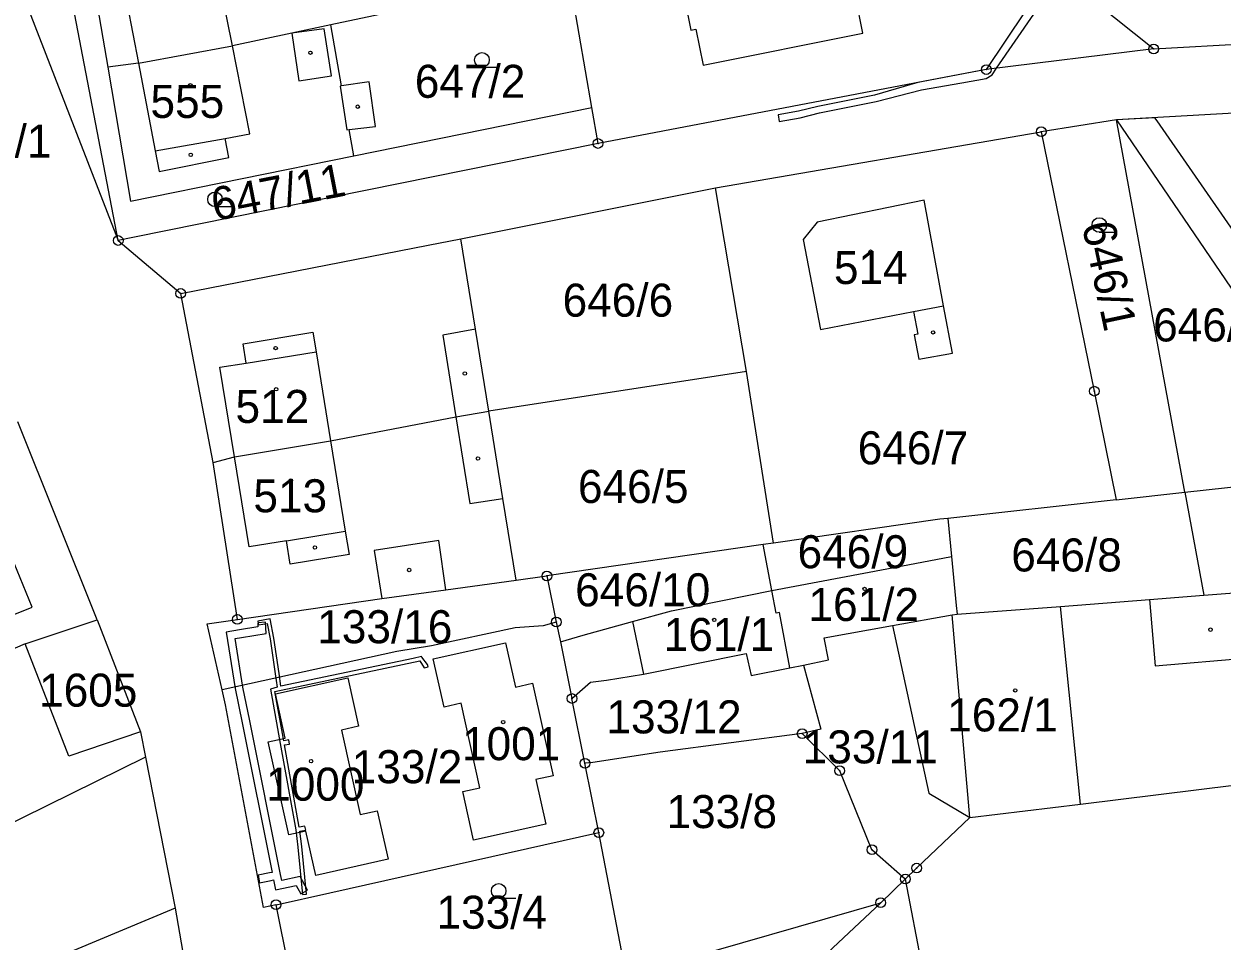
# Model space of a CAD drawing. Extents: x -537341 to -532984, y -1143469 to -1141314.
# Drawn here: x -533782.7 to -533659.4, y -1143007.7 to -1142913.3 of the extents above; entities that cross this region are included whole.
import ezdxf

# ---------------------------------------------------------------- set-up
doc = ezdxf.new("R2010")
doc.units = 0
for name, color, linetype in [('Hranice parcel', 7, 'Continuous'), ('parcelní_č_2000', 7, 'Continuous'), ('Vnitřní kresba', 7, 'Continuous'), ('Věcná břemena k části', 7, 'Continuous'), ('Značky bodu BP', 7, 'Continuous'), ('Značky budov', 7, 'Continuous'), ('Značky kultur', 7, 'Continuous')]:
    doc.layers.add(name, color=color, linetype=linetype)

msp = doc.modelspace()

# ---------------------------------------------------------------- linework, layer by layer
at = {"layer": 'Hranice parcel'}
for p, q in [((-533786.13, -1142901.71), (-533773.02, -1142935.56)), ((-533773.02, -1142935.56), (-533779.04, -1142904.13)), ((-533776.44, -1142903.87), (-533774.1, -1142917.72)), ((-533726.64, -1142908.16), (-533751.13, -1142913.35)), ((-533724.28, -1142921.87), (-533726.64, -1142908.16)), ((-533666.46, -1142915.84), (-533560.9, -1142909.85)), ((-533770.94, -1142917.31), (-533761.27, -1142915.51)), ((-533666.46, -1142915.84), (-533683.69, -1142917.96)), ((-533770.94, -1142917.31), (-533774.1, -1142917.72)), ((-533683.69, -1142917.96), (-533723.64, -1142925.57)), ((-533748.78, -1142926.85), (-533724.28, -1142921.87)), ((-533723.64, -1142925.57), (-533724.28, -1142921.87)), ((-533670.28, -1142923.14), (-533678.04, -1142924.36)), ((-533663.27, -1142961.47), (-533670.28, -1142923.14)), ((-533711.54, -1142930.13), (-533678.04, -1142924.36)), ((-533737.77, -1142935.37), (-533711.54, -1142930.13)), ((-533708.36, -1142949.06), (-533711.54, -1142930.13)), ((-533773.02, -1142935.56), (-533766.59, -1142941.01)), ((-533763.26, -1142958.42), (-533766.59, -1142941.01)), ((-533708.36, -1142949.06), (-533734.89, -1142953.12)), ((-533705.6, -1142966.72), (-533708.36, -1142949.06)), ((-533775.17, -1142974.6), (-533783.36, -1142954.23)), ((-533663.27, -1142961.47), (-533629.48, -1142957.72)), ((-533760.76, -1142974.57), (-533763.26, -1142958.42)), ((-533670.31, -1142962.27), (-533687.66, -1142964.18)), ((-533670.31, -1142962.27), (-533663.27, -1142961.47)), ((-533663.27, -1142961.47), (-533661.32, -1142972.07)), ((-533687.66, -1142964.18), (-533687.28, -1142968.08)), ((-533706.65, -1142966.87), (-533728.91, -1142970.09)), ((-533705.6, -1142966.72), (-533706.65, -1142966.87)), ((-533705.76, -1142971.6), (-533706.65, -1142966.87)), ((-533739.31, -1142971.52), (-533732.07, -1142970.51)), ((-533732.07, -1142970.51), (-533728.91, -1142970.09)), ((-533728.91, -1142970.09), (-533727.94, -1142974.84)), ((-533716.09, -1142973.67), (-533705.76, -1142971.6)), ((-533686.69, -1142974.04), (-533676.05, -1142973.23)), ((-533673.99, -1142993.57), (-533676.05, -1142973.23)), ((-533782.58, -1142977.08), (-533775.17, -1142974.6)), ((-533775.17, -1142974.6), (-533770.72, -1142986.14)), ((-533727.94, -1142974.84), (-533727.52, -1142976.87)), ((-533727.52, -1142976.87), (-533726.33, -1142982.71)), ((-533703.91, -1142979.55), (-533702.51, -1142979.27)), ((-533724.99, -1142989.38), (-533726.33, -1142982.71)), ((-533770.72, -1142986.14), (-533770.2, -1142988.74)), ((-533770.2, -1142988.74), (-533789.42, -1142998.21)), ((-533770.2, -1142988.74), (-533767.15, -1143004.29)), ((-533723.56, -1142996.52), (-533724.99, -1142989.38)), ((-533685.4, -1142994.95), (-533673.99, -1142993.57)), ((-533720.72, -1143011.28), (-533723.56, -1142996.52)), ((-533694.56, -1143003.73), (-533692.03, -1143001.3)), ((-533692.03, -1143001.3), (-533689.17, -1143016.19)), ((-533767.15, -1143004.29), (-533764.49, -1143019.94)), ((-533754.02, -1143017.55), (-533756.78, -1143003.94)), ((-533717.21, -1143010.27), (-533694.56, -1143003.73)), ((-533694.56, -1143003.73), (-533712.73, -1143020.79))]:
    msp.add_line(p, q, dxfattribs=at)
for points in [[(-533689.87, -1142816.17), (-533672.51, -1142910.99), (-533666.46, -1142915.84)], [(-533684.34, -1142886.86), (-533679.73, -1142912.01), (-533683.69, -1142917.96)], [(-533714.09, -1142913.89), (-533713.58, -1142913.79), (-533712.81, -1142917.52), (-533696.39, -1142914.21), (-533697.12, -1142910.54), (-533696.62, -1142910.44), (-533697.36, -1142906.7), (-533697.86, -1142906.8), (-533698.59, -1142903.13), (-533715.11, -1142906.43), (-533714.36, -1142910.04), (-533714.86, -1142910.14), (-533714.09, -1142913.89)], [(-533761.27, -1142915.51), (-533763.48, -1142904.48), (-533770.82, -1142905.89), (-533770.44, -1142907.79), (-533772.69, -1142908.22), (-533770.94, -1142917.31)], [(-533751.13, -1142913.35), (-533755.17, -1142914.21), (-533761.27, -1142915.51)], [(-533748.78, -1142926.85), (-533749.25, -1142924.14), (-533746.54, -1142923.83), (-533747.21, -1142919.21), (-533750.04, -1142919.64), (-533751.13, -1142913.35)], [(-533521.33, -1142914.7), (-533670.28, -1142923.14)], [(-533774.1, -1142917.72), (-533771.76, -1142931.52), (-533748.78, -1142926.85)], [(-533678.04, -1142924.36), (-533672.58, -1142951.07), (-533670.31, -1142962.27)], [(-533723.64, -1142925.57), (-533771.52, -1142935.25), (-533773.02, -1142935.56)], [(-533702.52, -1142935.45), (-533700.76, -1142944.72), (-533691.18, -1142942.87), (-533690.72, -1142945.2), (-533691.12, -1142945.28), (-533690.63, -1142947.79), (-533687.17, -1142947.14), (-533688.08, -1142942.27), (-533690.1, -1142931.39), (-533701.11, -1142933.66), (-533702.52, -1142935.45)], [(-533766.59, -1142941.01), (-533741.13, -1142936.04), (-533737.77, -1142935.37)], [(-533734.89, -1142953.12), (-533736.26, -1142944.69), (-533737.77, -1142935.37)], [(-533763.26, -1142958.42), (-533761.06, -1142957.84), (-533751.16, -1142956.19), (-533738.28, -1142953.72), (-533734.89, -1142953.12)], [(-533732.07, -1142970.51), (-533733.43, -1142962.11), (-533734.89, -1142953.12)], [(-533790.37, -1142976.72), (-533781.88, -1142973.31), (-533784.96, -1142965.77), (-533785.37, -1142965.94), (-533786.04, -1142964.31), (-533784.92, -1142963.83), (-533786.62, -1142959.65), (-533798.56, -1142964.49), (-533796.62, -1142969.19), (-533793.82, -1142968.09), (-533790.37, -1142976.72)], [(-533687.66, -1142964.18), (-533688.46, -1142964.26), (-533705.6, -1142966.72)], [(-533705.76, -1142971.6), (-533693.93, -1142969.35), (-533687.28, -1142968.08)], [(-533687.28, -1142968.08), (-533686.78, -1142973.15), (-533686.69, -1142974.04)], [(-533661.32, -1142972.07), (-533654.63, -1142971.54), (-533631.89, -1142969.71), (-533631.9, -1142969.41), (-533631.01, -1142969.31)], [(-533760.76, -1142974.57), (-533745.89, -1142972.42), (-533739.31, -1142971.52)], [(-533703.91, -1142979.55), (-533704.97, -1142973.85), (-533705.33, -1142973.92), (-533705.76, -1142971.6)], [(-533676.05, -1142973.23), (-533666.9, -1142972.52), (-533661.32, -1142972.07)], [(-533727.52, -1142976.87), (-533725.19, -1142976.19), (-533720.09, -1142974.78), (-533716.09, -1142973.67)], [(-533762.32, -1142981.8), (-533763.85, -1142975.03), (-533760.76, -1142974.57)], [(-533727.94, -1142974.84), (-533729.28, -1142975.22), (-533732.16, -1142975.44), (-533740.78, -1142977.29), (-533744.36, -1142977.88), (-533762.32, -1142981.8)], [(-533685.4, -1142994.95), (-533687.19, -1142974.08), (-533686.69, -1142974.04)], [(-533702.51, -1142979.27), (-533699.93, -1142978.74), (-533700.39, -1142976.47), (-533693.34, -1142975.19), (-533689.59, -1142992.44), (-533685.4, -1142994.95)], [(-533782.58, -1142977.08), (-533803.91, -1142986.3), (-533833.25, -1143001.47), (-533840.7, -1143005.22)], [(-533770.72, -1142986.14), (-533778.11, -1142988.66), (-533782.58, -1142977.08)], [(-533730.38, -1142981.13), (-533728.27, -1142990.68), (-533730.03, -1142991.06), (-533729.01, -1142995.63), (-533736.46, -1142997.3), (-533737.57, -1142992.3), (-533735.82, -1142991.89), (-533737.74, -1142983.2), (-533739.49, -1142983.6), (-533740.6, -1142978.61), (-533733.17, -1142976.98), (-533732.13, -1142981.53), (-533730.38, -1142981.13)], [(-533726.33, -1142982.71), (-533724.42, -1142981.03), (-533722.77, -1142980.82), (-533718.95, -1142980.22), (-533708.39, -1142978.07), (-533707.88, -1142980.35), (-533703.91, -1142979.55)], [(-533702.51, -1142979.27), (-533700.71, -1142985.88), (-533702.64, -1142986.32)], [(-533746.37, -1142994.26), (-533745.25, -1142999.24), (-533752.68, -1143000.92), (-533753.72, -1142996.36), (-533755.46, -1142996.73), (-533757.6, -1142987.18), (-533755.85, -1142986.78), (-533756.84, -1142982.23), (-533749.4, -1142980.57), (-533748.31, -1142985.57), (-533750.06, -1142985.96), (-533748.12, -1142994.65), (-533746.37, -1142994.26)], [(-533756.78, -1143003.94), (-533758.07, -1143004.23), (-533761.97, -1142983.36), (-533762.32, -1142981.8)], [(-533702.64, -1142986.32), (-533717.24, -1142988.22), (-533724.17, -1142989.29), (-533724.99, -1142989.38)], [(-533692.03, -1143001.3), (-533695.46, -1142998.28), (-533698.77, -1142990.14), (-533702.64, -1142986.32)], [(-533673.99, -1142993.57), (-533649.93, -1142990.6), (-533632.85, -1142987.8), (-533629.95, -1142988.83)], [(-533685.4, -1142994.95), (-533690.86, -1143000.17), (-533692.03, -1143001.3)], [(-533756.78, -1143003.94), (-533751.23, -1143002.7), (-533723.56, -1142996.52)], [(-533767.15, -1143004.29), (-533798.9, -1143017.55), (-533822.76, -1143028.59)]]:
    msp.add_lwpolyline(points, dxfattribs=at)
at = {"layer": 'Vnitřní kresba'}
for p, q in [((-533751.81, -1142913.75), (-533755.17, -1142914.21)), ((-533755.17, -1142914.21), (-533754.44, -1142919.12)), ((-533751.07, -1142918.6), (-533751.81, -1142913.75)), ((-533759.46, -1142924.59), (-533761.27, -1142915.51)), ((-533770.94, -1142917.31), (-533769.21, -1142926.33)), ((-533754.44, -1142919.12), (-533751.07, -1142918.6)), ((-533750.04, -1142919.64), (-533750.17, -1142919.66)), ((-533750.17, -1142919.66), (-533749.48, -1142924.16)), ((-533749.48, -1142924.16), (-533749.25, -1142924.14)), ((-533769.21, -1142926.33), (-533762.03, -1142925.05)), ((-533762.03, -1142925.05), (-533759.46, -1142924.59)), ((-533761.64, -1142927.02), (-533762.03, -1142925.05)), ((-533769.21, -1142926.33), (-533768.8, -1142928.45)), ((-533768.8, -1142928.45), (-533761.64, -1142927.02)), ((-533691.18, -1142942.87), (-533688.08, -1142942.27)), ((-533760.15, -1142946.18), (-533752.98, -1142944.98)), ((-533752.98, -1142944.98), (-533752.65, -1142947.01)), ((-533736.26, -1142944.69), (-533739.63, -1142945.32)), ((-533739.63, -1142945.32), (-533738.28, -1142953.72)), ((-533759.85, -1142948.17), (-533760.15, -1142946.18)), ((-533759.85, -1142948.17), (-533752.65, -1142947.01)), ((-533752.65, -1142947.01), (-533751.16, -1142956.19)), ((-533762.55, -1142948.61), (-533759.85, -1142948.17)), ((-533761.06, -1142957.84), (-533762.55, -1142948.61)), ((-533738.28, -1142953.72), (-533736.84, -1142962.63)), ((-533751.16, -1142956.19), (-533749.66, -1142965.48)), ((-533759.56, -1142967.08), (-533761.06, -1142957.84)), ((-533736.84, -1142962.63), (-533733.43, -1142962.11)), ((-533755.7, -1142966.46), (-533749.66, -1142965.48)), ((-533749.66, -1142965.48), (-533749.27, -1142967.9)), ((-533755.7, -1142966.46), (-533759.56, -1142967.08)), ((-533755.31, -1142968.88), (-533755.7, -1142966.46)), ((-533740.02, -1142966.44), (-533746.68, -1142967.47)), ((-533746.68, -1142967.47), (-533745.89, -1142972.42)), ((-533739.31, -1142971.52), (-533740.02, -1142966.44)), ((-533749.27, -1142967.9), (-533755.31, -1142968.88)), ((-533666.9, -1142972.52), (-533666.32, -1142979.34)), ((-533720.09, -1142974.78), (-533718.95, -1142980.22)), ((-533693.34, -1142975.19), (-533687.19, -1142974.08)), ((-533666.32, -1142979.34), (-533654.03, -1142978.3))]:
    msp.add_line(p, q, dxfattribs=at)
at = {"layer": 'Věcná břemena k části'}
msp.add_lwpolyline([(-533679.73, -1142912.01), (-533683.69, -1142917.96), (-533690.72, -1142919.3), (-533695.2, -1142920.58), (-533701.01, -1142921.75), (-533703, -1142922.26), (-533705.1, -1142922.61), (-533704.99, -1142923.3), (-533702.86, -1142922.94), (-533700.85, -1142922.43), (-533695.04, -1142921.26), (-533690.36, -1142920.06), (-533686.2, -1142919.31), (-533683.71, -1142918.89), (-533683.09, -1142918.5), (-533682.63, -1142917.83), (-533678.79, -1142912.25)], dxfattribs=at)
for points in [[(-533642.29, -1142959.14), (-533632.47, -1142958.05), (-533638.27, -1142956.15), (-533647, -1142950.83), (-533666.12, -1142923.25), (-533666.35, -1142922.92), (-533670.28, -1142923.14), (-533650, -1142952.97)], [(-533753.53, -1143002.43), (-533754.28, -1143001.04), (-533756.2, -1143001.45), (-533756.32, -1143000.84), (-533759.49, -1142985.02), (-533760.19, -1142981.55), (-533761, -1142976.53), (-533760.35, -1142976.43), (-533757.78, -1142976), (-533757.87, -1142974.85), (-533758.67, -1142974.92), (-533758.64, -1142975.33), (-533760.53, -1142975.64), (-533761.92, -1142975.88), (-533760.98, -1142981.69), (-533760.27, -1142985.22), (-533757.18, -1143000.61), (-533757.44, -1143000.66), (-533758.63, -1143000.89), (-533758.49, -1143001.68), (-533757.29, -1143001.44), (-533757.03, -1143001.39), (-533756.84, -1143002.41), (-533754.7, -1143001.95), (-533754.24, -1143002.81)], [(-533758.64, -1142974.75), (-533758.57, -1142975.14), (-533757.7, -1142974.98), (-533757.4, -1142976.58), (-533756.87, -1142980.18), (-533756.67, -1142981.53), (-533757.35, -1142981.74), (-533756.34, -1142987.35), (-533754.74, -1142996.22), (-533754.52, -1142998.01), (-533754.05, -1143002.88), (-533753.65, -1143002.84), (-533754.12, -1142997.96), (-533754.32, -1142996.37), (-533753.72, -1142996.26), (-533753.81, -1142995.86), (-533754.39, -1142995.95), (-533755.91, -1142987.47), (-533755.39, -1142987.4), (-533755.46, -1142986.98), (-533755.99, -1142987.06), (-533756.9, -1142982), (-533741.97, -1142978.84), (-533741.53, -1142979.54), (-533741.14, -1142979.44), (-533741.2, -1142979.2), (-533741.76, -1142978.47), (-533741.82, -1142978.4), (-533742.66, -1142978.58), (-533756.28, -1142981.43), (-533756.47, -1142980.13), (-533757, -1142976.51), (-533757.37, -1142974.51)]]:
    msp.add_lwpolyline(points, close=True, dxfattribs=at)
at = {"layer": 'Značky bodu BP'}
for centre, radius in [((-533666.46, -1142915.84), 0.5), ((-533666.46, -1142915.84), 0.0303), ((-533683.69, -1142917.96), 0.5), ((-533683.69, -1142917.96), 0.0303), ((-533678.04, -1142924.36), 0.5), ((-533678.04, -1142924.36), 0.0303), ((-533723.64, -1142925.57), 0.5), ((-533723.64, -1142925.57), 0.0303), ((-533773.02, -1142935.56), 0.5), ((-533773.02, -1142935.56), 0.0303), ((-533766.59, -1142941.01), 0.5), ((-533766.59, -1142941.01), 0.0303), ((-533672.58, -1142951.07), 0.5), ((-533672.58, -1142951.07), 0.0303), ((-533728.91, -1142970.09), 0.5), ((-533728.91, -1142970.09), 0.0303), ((-533760.76, -1142974.57), 0.5), ((-533760.76, -1142974.57), 0.0303), ((-533727.94, -1142974.84), 0.5), ((-533727.94, -1142974.84), 0.0303), ((-533726.33, -1142982.71), 0.5), ((-533726.33, -1142982.71), 0.0303), ((-533702.64, -1142986.32), 0.5), ((-533702.64, -1142986.32), 0.0303), ((-533724.99, -1142989.38), 0.5), ((-533724.99, -1142989.38), 0.0303), ((-533698.77, -1142990.14), 0.5), ((-533698.77, -1142990.14), 0.0303), ((-533723.56, -1142996.52), 0.5), ((-533723.56, -1142996.52), 0.0303), ((-533695.46, -1142998.28), 0.5), ((-533695.46, -1142998.28), 0.0303), ((-533690.86, -1143000.17), 0.5), ((-533692.03, -1143001.3), 0.5), ((-533690.86, -1143000.17), 0.0303), ((-533692.03, -1143001.3), 0.0303), ((-533694.56, -1143003.73), 0.5), ((-533756.78, -1143003.94), 0.5), ((-533756.78, -1143003.94), 0.0303), ((-533694.56, -1143003.73), 0.0303)]:
    msp.add_circle(centre, radius, dxfattribs=at)
at = {"layer": 'Značky budov'}
for centre in [(-533753.24, -1142916.23), (-533765.6, -1142919.58), (-533748.37, -1142921.78), (-533765.56, -1142926.74), (-533695.59, -1142936.71), (-533689.17, -1142945.02), (-533756.82, -1142946.63), (-533737.35, -1142949.25), (-533756.77, -1142950.87), (-533736, -1142958), (-533755.26, -1142960.26), (-533752.78, -1142967.16), (-533743.08, -1142969.48), (-533696.22, -1142971.43), (-533711.69, -1142974.62), (-533660.62, -1142975.62), (-533680.71, -1142981.88), (-533733.41, -1142985.14), (-533753.17, -1142989.16)]:
    msp.add_circle(centre, 0.175, dxfattribs=at)
at = {"layer": 'Značky kultur'}
for p, q in [((-533735.59, -1142917.72), (-533733.84, -1142917.72)), ((-533763.06, -1142932.07), (-533761.31, -1142932.07)), ((-533672.06, -1142934.71), (-533670.31, -1142934.71)), ((-533733.87, -1143003.26), (-533732.12, -1143003.26))]:
    msp.add_line(p, q, dxfattribs=at)
for centre in [(-533735.59, -1142916.97), (-533763.06, -1142931.32), (-533672.06, -1142933.96), (-533733.87, -1143002.51)]:
    msp.add_circle(centre, 0.75, dxfattribs=at)

# ---------------------------------------------------------------- texts
at = {"layer": 'parcelní_č_2000'}
for s, p in [('647/2', (-533742.5, -1142920.87)), ('555', (-533769.7, -1142922.94)), ('1344/1', (-533793.8, -1142927.03)), ('514', (-533699.37, -1142940.04)), ('646/6', (-533727.29, -1142943.4)), ('646/3', (-533666.52, -1142945.95)), ('512', (-533760.95, -1142954.34)), ('646/7', (-533696.92, -1142958.6)), ('513', (-533759.11, -1142963.54)), ('646/5', (-533725.71, -1142962.58)), ('646/9', (-533703.11, -1142969.3)), ('646/8', (-533681.12, -1142969.63)), ('646/10', (-533726, -1142973.22)), ('161/2', (-533701.99, -1142974.73)), ('133/16', (-533752.54, -1142977.02)), ('161/1', (-533716.89, -1142977.82)), ('1605', (-533781.16, -1142983.55)), ('133/12', (-533722.78, -1142986.3)), ('162/1', (-533687.71, -1142986.1)), ('1001', (-533737.64, -1142989.06)), ('133/11', (-533702.58, -1142989.39)), ('133/2', (-533748.99, -1142991.43)), ('1000', (-533757.79, -1142993.23)), ('133/8', (-533716.6, -1142996.05)), ('133/4', (-533740.27, -1143006.41))]:
    msp.add_text(s, height=3.4, dxfattribs=at).set_placement(p)
for s, rotation, p in [('647/11', 11, (-533763.08, -1142933.56)), ('646/1', 282, (-533673.87, -1142933.94))]:
    msp.add_text(s, height=3.4, rotation=rotation, dxfattribs=at).set_placement(p)

doc.saveas('drawing.dxf')
